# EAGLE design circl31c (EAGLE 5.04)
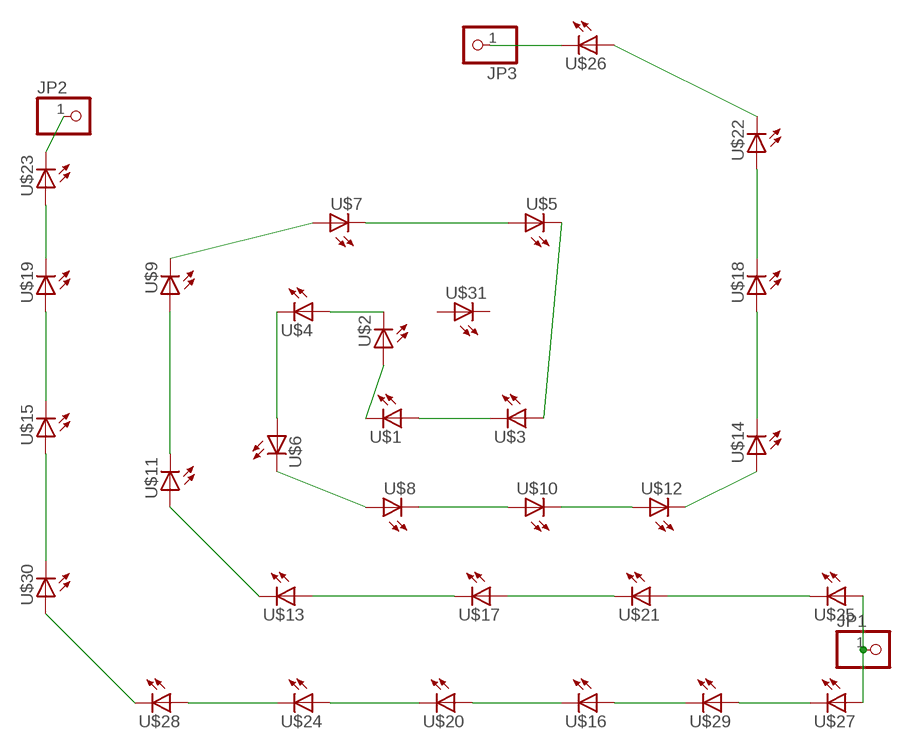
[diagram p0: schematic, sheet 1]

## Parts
JP1  PINHD-1X1  [1X01]
JP2  PINHD-1X1  [1X01]
JP3  PINHD-1X1  [1X01]
U$1  LED5MM  [LED5MM]
U$2  LED5MM  [LED5MM]
U$3  LED5MM  [LED5MM]
U$4  LED5MM  [LED5MM]
U$5  LED5MM  [LED5MM]
U$6  LED5MM  [LED5MM]
U$7  LED5MM  [LED5MM]
U$8  LED5MM  [LED5MM]
U$9  LED5MM  [LED5MM]
U$10  LED5MM  [LED5MM]
U$11  LED5MM  [LED5MM]
U$12  LED5MM  [LED5MM]
U$13  LED5MM  [LED5MM]
U$14  LED5MM  [LED5MM]
U$15  LED5MM  [LED5MM]
U$16  LED5MM  [LED5MM]
U$17  LED5MM  [LED5MM]
U$18  LED5MM  [LED5MM]
U$19  LED5MM  [LED5MM]
U$20  LED5MM  [LED5MM]
U$21  LED5MM  [LED5MM]
U$22  LED5MM  [LED5MM]
U$23  LED5MM  [LED5MM]
U$24  LED5MM  [LED5MM]
U$25  LED5MM  [LED5MM]
U$26  LED5MM  [LED5MM]
U$27  LED5MM  [LED5MM]
U$28  LED5MM  [LED5MM]
U$29  LED5MM  [LED5MM]
U$30  LED5MM  [LED5MM]
U$31  LED5MM  [LED5MM]

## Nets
N$1: U$1.A U$3.K(C)
N$2: U$3.A U$5.K(C)
N$3: U$5.A U$7.K(C)
N$4: U$7.A U$9.K(C)
N$5: U$9.A U$11.K(C)
N$6: U$11.A U$13.K(C)
N$7: U$13.A U$17.K(C)
N$8: U$17.A U$21.K(C)
N$9: U$21.A U$25.K(C)
N$10: U$1.K(C) U$2.A
N$11: U$2.K(C) U$4.A
N$12: U$4.K(C) U$6.A
N$13: U$6.K(C) U$8.A
N$14: U$8.K(C) U$10.A
N$15: U$10.K(C) U$12.A
N$16: U$12.K(C) U$14.A
N$17: U$14.K(C) U$18.A
N$18: U$18.K(C) U$22.A
N$19: U$22.K(C) U$26.A
N$20: JP1.1 U$25.A U$27.A
N$21: U$27.K(C) U$29.A
N$22: U$16.A U$29.K(C)
N$23: U$16.K(C) U$20.A
N$24: U$20.K(C) U$24.A
N$25: U$24.K(C) U$28.A
N$26: U$28.K(C) U$30.A
N$27: U$15.A U$30.K(C)
N$28: U$15.K(C) U$19.A
N$29: U$19.K(C) U$23.A
N$30: JP2.1 U$23.K(C)
N$31: JP3.1 U$26.K(C)
Unconnected: U$31.A U$31.K(C)

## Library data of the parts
JP1-JP3 = pinhead:PINHD-1X1: PIN HEADER
U$1-U$31 = led(2):LED: LED

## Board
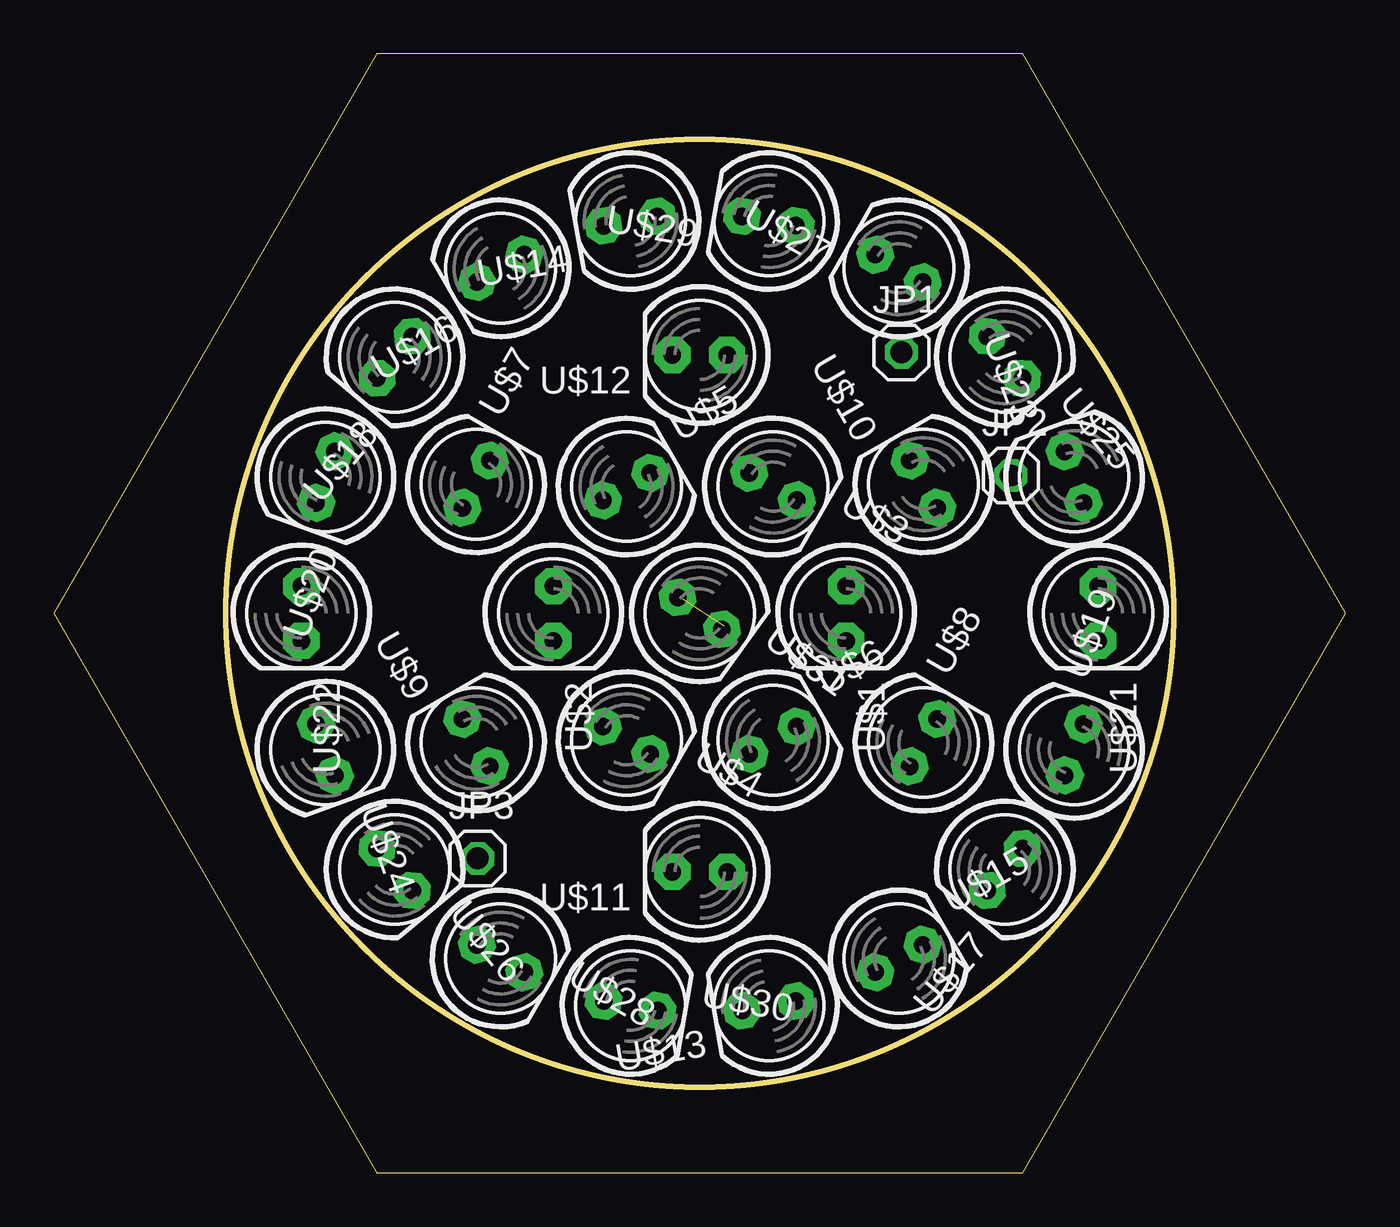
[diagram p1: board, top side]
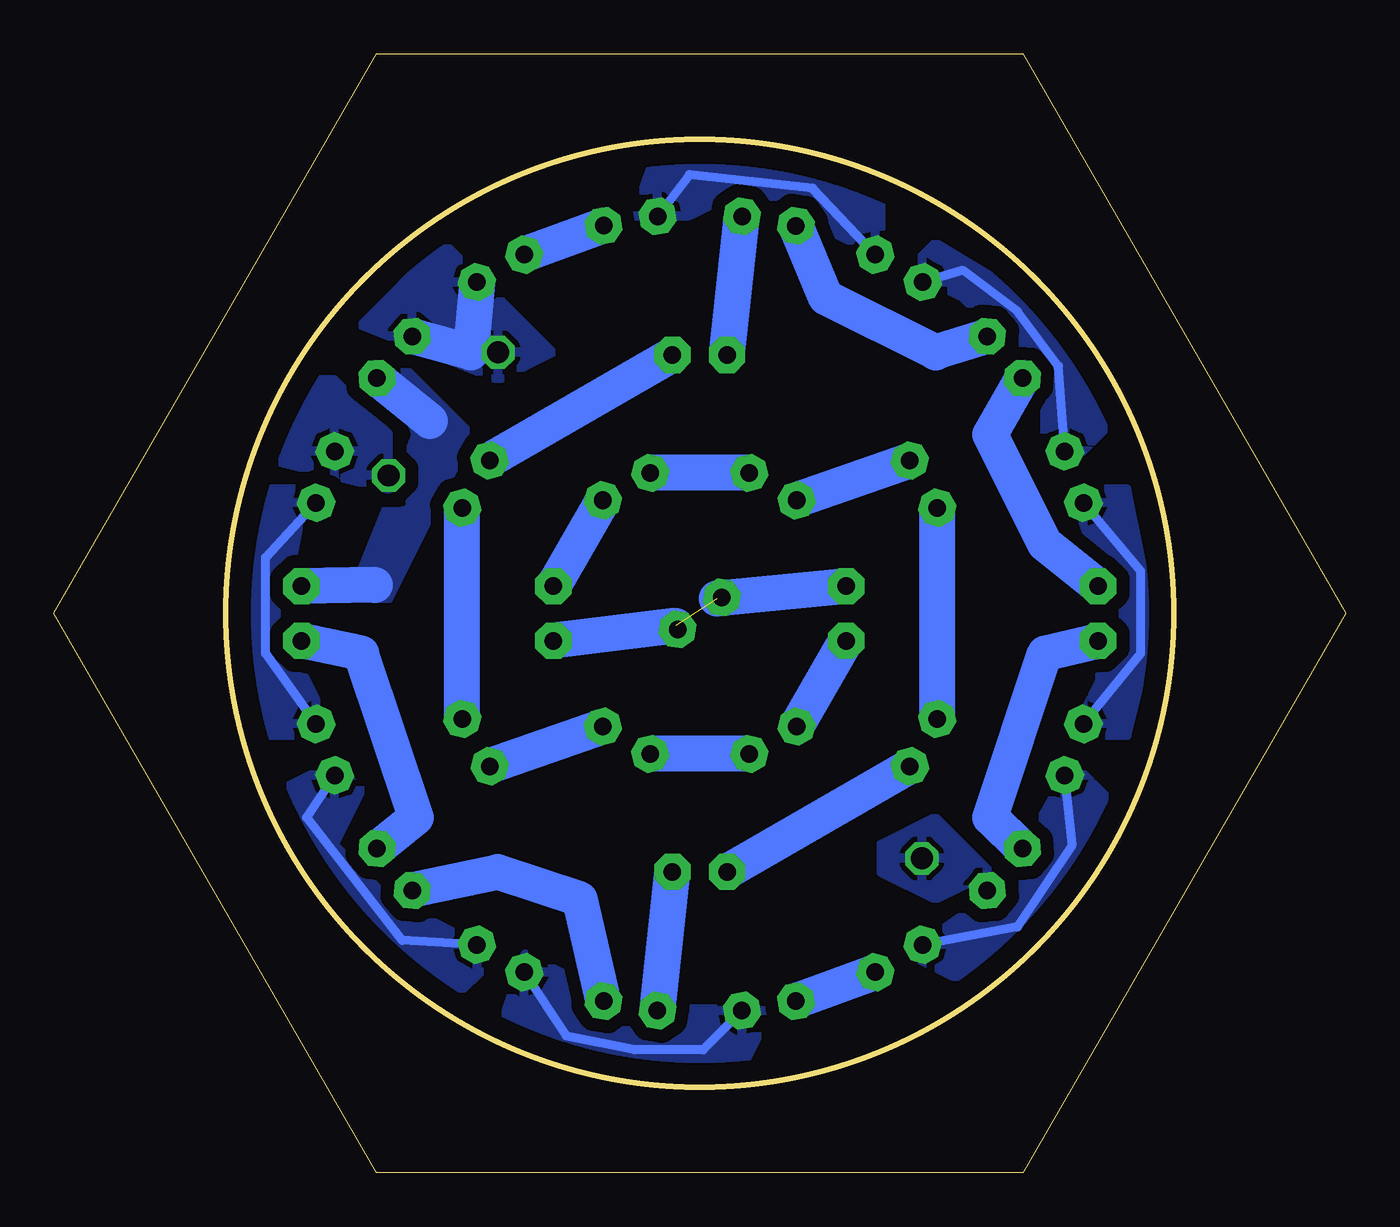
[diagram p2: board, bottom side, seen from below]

Size 60 x 51.96 mm. Coordinates in mm from the lower left corner, seen from the top.
Outline: 15,0 45,0 60,25.98 45,51.96 15,51.96 0,25.98 15,0
Outline: circle at 30,25.98 radius 22
Copper layers (1*16): Top 0.035mm / dielectric 1.5mm / Bottom 0.035mm
Design rules "default": minimum track width 10mil, minimum drill 24mil, track to track 8mil, track to pad 8mil, pad to pad 8mil, via to via 8mil, smd to smd 8mil, copper to edge 40mil, drill to drill 8mil, minimum pad ring 10mil, minimum via ring 8mil, stop-mask expansion 4mil, vias tented up to drill 0mil, thermal gap 10mil

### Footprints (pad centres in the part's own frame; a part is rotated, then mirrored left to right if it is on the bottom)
1X01 = drill 1.016 octagon: 1 0,0
LED5MM = drill 0.813 pad 1.676 octagon: A -1.27,0; K 1.27,0

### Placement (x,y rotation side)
JP1  39.37,38.1 0 top
JP2  44.45,32.38 0 top
JP3  19.68,14.61 0 top
U$1  36.8,25.98 270 top
U$2  23.2,25.98 270 top
U$3  33.4,31.87 330 top
U$4  26.6,20.09 330 top
U$5  26.6,31.87 30 top
U$6  33.4,20.09 30 top
U$7  19.61,31.98 59.9 top
U$8  40.39,19.98 59.9 top
U$9  19.61,19.98 120 top
U$10  40.39,31.98 120 top
U$11  30,13.98 180 top
U$12  30,37.98 180 top
U$13  33.21,7.76 190 top
U$14  26.79,44.2 190 top
U$15  39.25,9.96 30 top
U$16  20.75,42 210 top
U$17  44.17,14.09 230 top
U$18  15.83,37.87 230 top
U$19  47.38,19.65 70 top
U$20  12.62,32.31 250 top
U$21  48.5,25.98 270 top
U$22  11.5,25.98 270 top
U$23  47.38,32.31 110 top
U$24  12.62,19.65 290 top
U$25  44.17,37.87 310 top
U$26  15.83,14.09 310 top
U$27  39.25,42 150 top
U$28  20.75,9.96 330 top
U$29  33.21,44.2 170.1 top
U$30  26.79,7.76 350.1 top
U$31  30,25.98 324.1 top

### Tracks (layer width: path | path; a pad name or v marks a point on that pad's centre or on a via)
N$1
  Bottom 1.676: U$1.A U$3.K
N$2
  Bottom 1.676: U$5.K U$3.A
N$3
  Bottom 1.676: U$7.K U$5.A
N$4
  Bottom 1.676: U$9.K U$7.A
N$5
  Bottom 1.676: U$9.A U$11.K
N$6
  Bottom 1.676: U$13.K U$11.A
N$7
  Bottom 1.676: U$13.A 35.56,12.7 39.37,13.97 U$17.K
N$8
  Bottom 1.676: U$17.A 43.18,16.51 45.72,24.13 U$21.K
N$9
  Bottom 1.676: 45.09,27.3 U$21.A | 42.55,34.92 U$25.K
  pour Bottom (isolate 0.61, rank 3): 44.45,38.1 40.64,34.29 44.45,26.67 49.53,26.67 49.53,27.94 45.72,27.94 43.18,34.29
N$10  (1 unrouted)
  Bottom 1.676: U$2.A 29.21,26.67 | 31.11,25.4 U$1.K
N$11
  Bottom 1.676: U$4.A U$2.K
N$12
  Bottom 1.676: U$4.K U$6.A
N$13
  Bottom 1.676: U$6.K U$8.A
N$14
  Bottom 1.676: U$8.K U$10.A
N$15
  Bottom 1.676: U$12.A U$10.K
N$16
  Bottom 1.676: U$12.K U$14.A
N$17
  Bottom 1.676: U$18.A 19.05,38.1 24.13,40.64 U$14.K
N$18
  Bottom 1.676: U$18.K 16.51,34.29 13.97,29.21 U$22.A
N$19
  Bottom 1.676: U$22.K 13.97,24.13 16.51,16.51 U$26.A
N$20
  Bottom 1.676: U$25.A 40.64,38.1 U$27.A
  pour Bottom (isolate 0.61, rank 2): 41.91,43.18 45.72,39.37 39.37,36.83 36.83,38.1
N$21
  Bottom 1.676: U$29.A U$27.K
N$22
  Bottom 0.406: U$29.K 30.48,46.35 24.77,45.72 U$16.A
  pour Bottom (isolate 0.61): 21.59,43.18 21.59,45.72 25.4,46.99 31.75,48.26 33.02,44.45 30.48,44.45 27.94,45.72 22.86,43.18
N$23
  Bottom 0.406: U$20.A 13.34,37.47 15.24,40.01 17.78,41.91 U$16.K
  pour Bottom (isolate 0.61): 20.32,41.91 19.05,43.18 12.7,39.37 10.16,35.56 12.7,33.02 13.97,34.29 13.97,36.83 17.78,40.64
N$24
  Bottom 0.406: U$24.A 9.53,24.13 9.53,27.94 U$20.K
  pour Bottom (isolate 0.61): 12.7,20.32 10.16,20.32 8.89,25.4 10.16,31.75 12.7,31.75 11.43,27.94 11.43,22.86
N$25
  Bottom 0.406: U$28.A 15.24,11.43 12.7,15.24 U$24.K
  pour Bottom (isolate 0.61): 12.7,19.05 10.79,17.14 13.34,12.7 17.78,8.89 20.32,10.16 15.88,13.34
N$26
  Bottom 1.676: U$28.K U$30.A
N$27
  Bottom 0.406: U$15.A 36.2,6.35 33.02,5.71 29.84,5.71 U$30.K
  pour Bottom (isolate 0.61): 26.67,7.62 27.94,5.08 33.02,5.08 39.37,6.35 38.1,10.16 33.02,7.62
N$28
  Bottom 0.406: U$19.A 48.26,16.51 43.81,10.79 U$15.K
  pour Bottom (isolate 0.61): 39.37,10.16 41.91,7.62 48.26,13.97 49.53,17.78 46.99,19.05 45.72,17.78 46.99,15.24 44.45,12.7
N$29
  Bottom 0.406: U$23.A 50.16,28.57 50.16,24.13 U$19.K
  pour Bottom (isolate 0.61): 48.26,31.75 50.8,31.75 52.07,25.4 50.8,20.32 46.99,20.32 49.53,25.4
N$30
  pour Bottom (isolate 0.61, rank 2): 46.99,36.83 48.26,36.83 49.53,33.02 44.45,31.75 44.45,34.29
N$31
  pour Bottom (isolate 0.61, rank 2): 16.51,13.97 19.05,16.51 21.59,15.24 21.59,13.97 19.05,12.7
